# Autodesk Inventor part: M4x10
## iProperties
Company: 한국ATC센터
Created: 2015-05
Part Number: M4x10
Document SubType Name: 모델링
Designer: KYOUNG IL JANG
Vendor: CBT Solutions
Author: KYOUNG IL JANG
Comments: 파생
